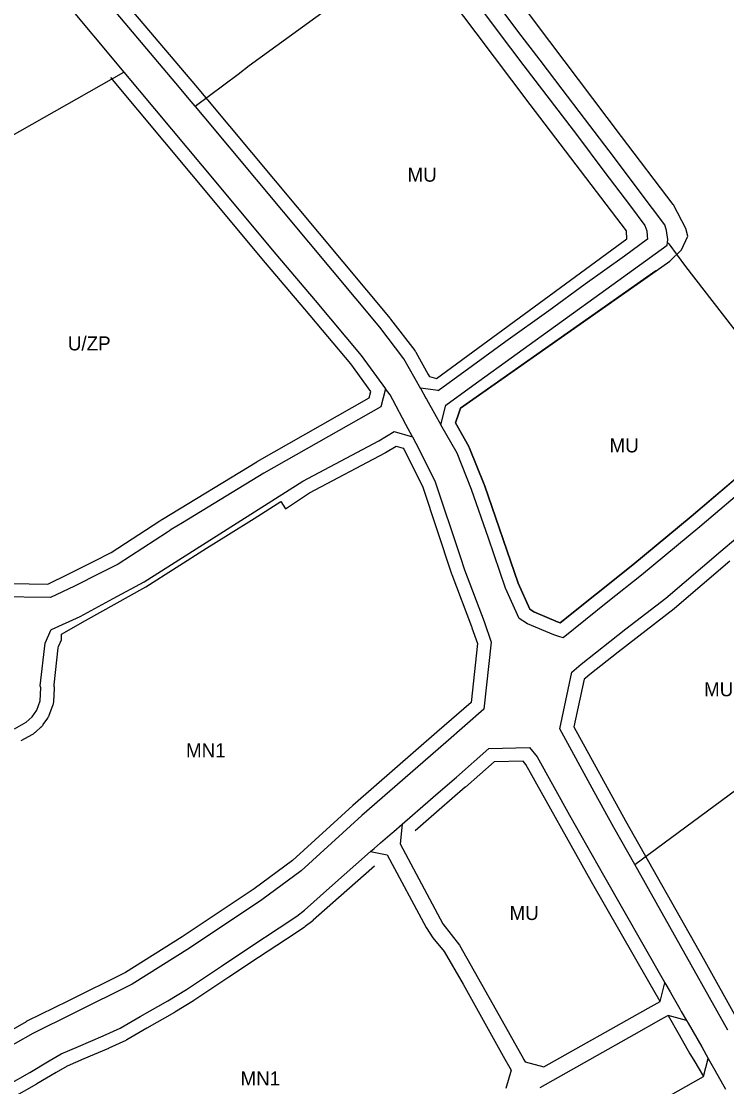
# Model space of a CAD drawing. Extents: x 7435758 to 7439981, y 5550649 to 5554049.
# Drawn here: x 7437381.1 to 7437642.5, y 5551609 to 5552003.8 of the extents above; entities that cross this region are included whole.
import ezdxf

# ---------------------------------------------------------------- set-up
doc = ezdxf.new("R2010")
doc.units = 0
for name, color, linetype in [('linie_rozgraniczające', 7, 'Continuous'), ('linie_zabudowy_nieprzekraczalne', 7, 'Continuous'), ('oznaczenia_przeznaczen', 7, 'Continuous')]:
    doc.layers.add(name, color=color, linetype=linetype)

msp = doc.modelspace()

# ---------------------------------------------------------------- linework, layer by layer
at = {"layer": 'linie_rozgraniczające'}
for p, q in [((7437465.45, 5551987.36), (7437526.53, 5552031.99)), ((7437395.89, 5552012.73), (7437419.08, 5551984.95)), ((7437438.35, 5551980.83), (7437411.17, 5552013.03)), ((7437547.91, 5552013.21), (7437557.39, 5552000.34)), ((7437565.08, 5552000.1), (7437556.73, 5552011.36)), ((7437557.39, 5552000.34), (7437567.31, 5551987.27)), ((7437573.33, 5551989.33), (7437565.08, 5552000.1)), ((7437461.37, 5551984.23), (7437465.45, 5551987.36)), ((7437567.31, 5551987.27), (7437577.08, 5551974.49)), ((7437581.47, 5551978.66), (7437573.33, 5551989.33)), ((7437311.16, 5551923.91), (7437419.08, 5551984.95)), ((7437419.08, 5551984.95), (7437448.05, 5551950.24)), ((7437445.45, 5551972.38), (7437461.37, 5551984.23)), ((7437441.54, 5551977.04), (7437438.35, 5551980.83)), ((7437589.82, 5551967.73), (7437581.47, 5551978.66)), ((7437443.31, 5551974.95), (7437441.54, 5551977.04)), ((7437445.45, 5551972.38), (7437443.31, 5551974.95)), ((7437577.08, 5551974.49), (7437587.18, 5551961.33)), ((7437445.64, 5551972.15), (7437445.45, 5551972.38)), ((7437448.82, 5551968.35), (7437445.64, 5551972.15)), ((7437487.61, 5551921.9), (7437448.82, 5551968.35)), ((7437600.85, 5551953.15), (7437589.82, 5551967.73)), ((7437587.18, 5551961.33), (7437596.99, 5551948.29)), ((7437610.36, 5551940.5), (7437600.85, 5551953.15)), ((7437448.05, 5551950.24), (7437475.42, 5551917.5)), ((7437596.99, 5551948.29), (7437606.8, 5551935.23)), ((7437619.5, 5551928.3), (7437610.36, 5551940.5)), ((7437606.8, 5551935.23), (7437612.15, 5551928.12)), ((7437612.15, 5551928.12), (7437612.9, 5551926.14)), ((7437620.15, 5551926.28), (7437619.5, 5551928.3)), ((7437613.15, 5551923.09), (7437604.55, 5551916.8)), ((7437612.9, 5551926.14), (7437613.06, 5551924.23)), ((7437613.06, 5551924.23), (7437613.15, 5551923.09)), ((7437620.7, 5551922.95), (7437620.15, 5551926.28)), ((7437620.55, 5551921.83), (7437620.7, 5551922.95)), ((7437513.95, 5551890.43), (7437487.61, 5551921.9)), ((7437597.68, 5551904.41), (7437620.42, 5551920.86)), ((7437620.42, 5551920.86), (7437620.55, 5551921.83)), ((7437620.55, 5551921.83), (7437620.98, 5551921.26)), ((7437620.98, 5551921.26), (7437627.25, 5551912.88)), ((7437475.42, 5551917.5), (7437489.95, 5551900.35)), ((7437604.55, 5551916.8), (7437590.08, 5551906.33)), ((7437627.25, 5551912.88), (7437651.38, 5551881.6)), ((7437590.08, 5551906.33), (7437576.52, 5551896.53)), ((7437581.25, 5551892.54), (7437597.68, 5551904.41)), ((7437489.95, 5551900.35), (7437507.05, 5551879.89)), ((7437576.52, 5551896.53), (7437560.63, 5551885.1)), ((7437564.88, 5551880.71), (7437581.25, 5551892.54)), ((7437522.88, 5551878.75), (7437513.95, 5551890.43)), ((7437560.63, 5551885.1), (7437548.22, 5551876.11)), ((7437507.05, 5551879.89), (7437516.05, 5551867.64)), ((7437548.38, 5551868.77), (7437564.88, 5551880.71)), ((7437529.07, 5551867.54), (7437522.88, 5551878.75)), ((7437548.22, 5551876.11), (7437535.57, 5551866.91)), ((7437516.05, 5551867.64), (7437514.27, 5551860.98)), ((7437517.73, 5551865.36), (7437516.05, 5551867.64)), ((7437535.56, 5551866.97), (7437528.99, 5551867.9)), ((7437528.99, 5551867.9), (7437529.07, 5551867.54)), ((7437529.07, 5551867.54), (7437530.96, 5551864.1)), ((7437538.33, 5551861.5), (7437548.38, 5551868.77)), ((7437518.71, 5551863.51), (7437517.73, 5551865.36)), ((7437523.62, 5551854.32), (7437518.71, 5551863.51)), ((7437530.96, 5551864.1), (7437531.18, 5551863.72)), ((7437531.18, 5551863.72), (7437534.16, 5551858.48)), ((7437535.57, 5551866.91), (7437535.56, 5551866.97)), ((7437514.27, 5551860.98), (7437470.98, 5551836.32)), ((7437536.52, 5551854.31), (7437538.33, 5551861.5)), ((7437534.16, 5551858.48), (7437536.52, 5551854.31)), ((7437513.52, 5551848.32), (7437519.26, 5551851.73)), ((7437519.26, 5551851.73), (7437525.99, 5551849.86)), ((7437525.99, 5551849.86), (7437523.62, 5551854.32)), ((7437542.53, 5551843.74), (7437536.52, 5551854.31)), ((7437485.44, 5551833.4), (7437513.52, 5551848.32)), ((7437525.99, 5551849.86), (7437527.24, 5551847.52)), ((7437527.24, 5551847.52), (7437534.32, 5551833.48)), ((7437547.96, 5551830.29), (7437542.53, 5551843.74)), ((7437665.96, 5551844.96), (7437632.46, 5551816.42)), ((7437470.98, 5551836.32), (7437440.82, 5551817.99)), ((7437426.54, 5551796.11), (7437485.44, 5551833.4)), ((7437534.32, 5551833.48), (7437543.64, 5551805.43)), ((7437554.15, 5551812.23), (7437547.96, 5551830.29)), ((7437440.82, 5551817.99), (7437436.65, 5551815.45)), ((7437632.46, 5551816.42), (7437610.86, 5551798.55)), ((7437640.35, 5551807.5), (7437653.28, 5551818.53)), ((7437435.2, 5551814.51), (7437416.9, 5551802.57)), ((7437435.93, 5551815.02), (7437435.2, 5551814.51)), ((7437436.65, 5551815.45), (7437435.93, 5551815.02)), ((7437560.51, 5551793.7), (7437554.15, 5551812.23)), ((7437543.64, 5551805.43), (7437545.26, 5551800.57)), ((7437619.9, 5551790.06), (7437640.35, 5551807.5)), ((7437416.9, 5551802.57), (7437410.33, 5551799.27)), ((7437545.26, 5551800.57), (7437552.55, 5551781.33)), ((7437410.33, 5551799.27), (7437400.82, 5551794.5)), ((7437610.86, 5551798.55), (7437598.45, 5551788.66)), ((7437400.82, 5551794.5), (7437391.92, 5551790.26)), ((7437415.15, 5551789.89), (7437426.54, 5551796.11)), ((7437565.52, 5551782.51), (7437560.51, 5551793.7)), ((7437391.92, 5551790.26), (7437362.95, 5551790.73)), ((7437402.89, 5551783.18), (7437415.15, 5551789.89)), ((7437598.45, 5551788.66), (7437581.81, 5551775.39)), ((7437605.15, 5551778.62), (7437619.9, 5551790.06)), ((7437392.24, 5551778.46), (7437402.89, 5551783.18)), ((7437552.55, 5551781.33), (7437555.16, 5551773.75)), ((7437568.68, 5551780.51), (7437565.52, 5551782.51)), ((7437389.94, 5551773.42), (7437392.15, 5551778.46)), ((7437392.15, 5551778.46), (7437392.24, 5551778.46)), ((7437578.38, 5551776.45), (7437568.68, 5551780.51)), ((7437599.12, 5551773.94), (7437605.15, 5551778.62)), ((7437388.11, 5551757.56), (7437389.94, 5551773.42)), ((7437555.16, 5551773.75), (7437552.52, 5551748.9)), ((7437580.32, 5551775.85), (7437578.38, 5551776.45)), ((7437581.81, 5551775.39), (7437580.32, 5551775.85)), ((7437588.51, 5551765.64), (7437599.12, 5551773.94)), ((7437586.77, 5551764.06), (7437588.51, 5551765.64)), ((7437580.6, 5551741.62), (7437585.14, 5551762.59)), ((7437585.14, 5551762.59), (7437586.77, 5551764.06)), ((7437388.32, 5551756.77), (7437388.11, 5551757.56)), ((7437608.38, 5551691.31), (7437697.86, 5551757.42)), ((7437388.11, 5551752.01), (7437388.32, 5551756.77)), ((7437386.77, 5551748.49), (7437388.11, 5551752.01)), ((7437382.91, 5551744.04), (7437385.05, 5551746.03)), ((7437385.05, 5551746.03), (7437386.77, 5551748.49)), ((7437552.52, 5551748.9), (7437538.38, 5551736.61)), ((7437378.55, 5551741.64), (7437382.91, 5551744.04)), ((7437593.36, 5551718.32), (7437580.6, 5551741.62)), ((7437538.38, 5551736.61), (7437527.95, 5551727.51)), ((7437542.31, 5551723.76), (7437554.35, 5551734.39)), ((7437554.35, 5551734.39), (7437569.37, 5551734.74)), ((7437569.37, 5551734.74), (7437572.2, 5551731.27)), ((7437572.2, 5551731.27), (7437584.28, 5551709.68)), ((7437527.95, 5551727.51), (7437507.26, 5551709.46)), ((7437534.68, 5551717.16), (7437542.31, 5551723.76)), ((7437600.61, 5551705.08), (7437593.36, 5551718.32)), ((7437522.25, 5551706.32), (7437532.65, 5551715.4)), ((7437532.65, 5551715.4), (7437534.68, 5551717.16)), ((7437584.28, 5551709.68), (7437596.77, 5551687.35)), ((7437507.26, 5551709.46), (7437484.74, 5551689.01)), ((7437519.07, 5551703.54), (7437522.25, 5551706.32)), ((7437522.25, 5551706.32), (7437521.46, 5551699.07)), ((7437514.23, 5551699.39), (7437518.5, 5551703.04)), ((7437518.5, 5551703.04), (7437519.07, 5551703.54)), ((7437608.38, 5551691.31), (7437600.61, 5551705.08)), ((7437511.81, 5551697.32), (7437514.23, 5551699.39)), ((7437521.46, 5551699.07), (7437537.32, 5551669.37)), ((7437495.3, 5551682.7), (7437510.51, 5551696.17)), ((7437510.51, 5551696.17), (7437511.81, 5551697.32)), ((7437510.51, 5551696.17), (7437516.65, 5551694.89)), ((7437516.65, 5551694.89), (7437531.04, 5551668.06)), ((7437629.36, 5551654.17), (7437608.38, 5551691.31)), ((7437484.74, 5551689.01), (7437470.2, 5551678.27)), ((7437596.77, 5551687.35), (7437618.93, 5551648.65)), ((7437485.95, 5551674.45), (7437495.3, 5551682.7)), ((7437470.2, 5551678.27), (7437443.4, 5551660.3)), ((7437483.17, 5551672.24), (7437485.95, 5551674.45)), ((7437476.57, 5551667.91), (7437483.17, 5551672.24)), ((7437466.18, 5551661.02), (7437476.57, 5551667.91)), ((7437531.04, 5551668.06), (7437533.57, 5551664.2)), ((7437537.32, 5551669.37), (7437543.45, 5551661.43)), ((7437533.57, 5551664.2), (7437537.74, 5551659.09)), ((7437443.4, 5551660.3), (7437422.12, 5551647)), ((7437455.22, 5551653.73), (7437466.18, 5551661.02)), ((7437537.74, 5551659.09), (7437544.83, 5551646.97)), ((7437543.45, 5551661.43), (7437557.1, 5551637.43)), ((7437442.25, 5551645.05), (7437455.22, 5551653.73)), ((7437642.86, 5551629.92), (7437629.36, 5551654.17)), ((7437422.12, 5551647), (7437400.48, 5551636.23)), ((7437544.83, 5551646.97), (7437560.31, 5551619.28)), ((7437617.81, 5551640.65), (7437619.59, 5551647.49)), ((7437618.93, 5551648.65), (7437619.59, 5551647.49)), ((7437619.59, 5551647.49), (7437621.5, 5551644.17)), ((7437435.36, 5551640.86), (7437442.25, 5551645.05)), ((7437621.5, 5551644.17), (7437622.11, 5551643.1)), ((7437622.11, 5551643.1), (7437625.09, 5551637.89)), ((7437425.1, 5551635.06), (7437435.36, 5551640.86)), ((7437613.33, 5551638.1), (7437617.81, 5551640.65)), ((7437400.48, 5551636.23), (7437385.3, 5551628.76)), ((7437417.69, 5551630.74), (7437425.1, 5551635.06)), ((7437557.1, 5551637.43), (7437567.16, 5551619.38)), ((7437574.65, 5551616.33), (7437613.33, 5551638.1)), ((7437620.74, 5551635.41), (7437618.01, 5551633.86)), ((7437627.56, 5551633.58), (7437620.74, 5551635.41)), ((7437625.09, 5551637.89), (7437625.65, 5551636.91)), ((7437625.65, 5551636.91), (7437627.56, 5551633.58)), ((7437411.37, 5551627.82), (7437417.69, 5551630.74)), ((7437618.01, 5551633.86), (7437608.04, 5551628.18)), ((7437627.56, 5551633.58), (7437628.17, 5551632.51)), ((7437628.17, 5551632.51), (7437633.2, 5551623.74)), ((7437385.3, 5551628.76), (7437365.21, 5551617.29)), ((7437402.23, 5551623.95), (7437411.37, 5551627.82)), ((7437608.04, 5551628.18), (7437573.23, 5551608.58)), ((7437395.88, 5551621.14), (7437402.23, 5551623.95)), ((7437633.2, 5551623.74), (7437635.6, 5551619.51)), ((7437391.43, 5551618.66), (7437395.88, 5551621.14)), ((7437560.31, 5551619.28), (7437562.05, 5551616.05)), ((7437567.16, 5551619.38), (7437567.22, 5551619.26)), ((7437567.22, 5551619.26), (7437567.79, 5551618.25)), ((7437633.83, 5551612.74), (7437635.6, 5551619.51)), ((7437635.6, 5551619.51), (7437638.09, 5551615.13)), ((7437384.27, 5551614.31), (7437391.43, 5551618.66)), ((7437562.56, 5551615.13), (7437560.61, 5551608.31)), ((7437562.05, 5551616.05), (7437562.56, 5551615.13)), ((7437567.79, 5551618.25), (7437574.65, 5551616.33)), ((7437638.09, 5551615.13), (7437642.09, 5551608.09)), ((7437375.99, 5551609.64), (7437384.27, 5551614.31)), ((7437578.11, 5551581.52), (7437633.83, 5551612.74))]:
    msp.add_line(p, q, dxfattribs=at)
at = {"layer": 'linie_zabudowy_nieprzekraczalne'}
for p, q in [((7437543.84, 5551860.45), (7437616.32, 5551911.33)), ((7437543.17, 5551858.56), (7437543.84, 5551860.45)), ((7437541.94, 5551855.04), (7437543.17, 5551858.56)), ((7437541.91, 5551854.96), (7437541.94, 5551855.04)), ((7437546.88, 5551846.21), (7437541.91, 5551854.96)), ((7437546.92, 5551846.13), (7437546.88, 5551846.21)), ((7437547.07, 5551845.84), (7437546.92, 5551846.13)), ((7437547.17, 5551845.61), (7437547.07, 5551845.84)), ((7437552.59, 5551832.16), (7437547.17, 5551845.61)), ((7437661.22, 5551847.49), (7437629.25, 5551820.25)), ((7437552.62, 5551832.09), (7437552.59, 5551832.16)), ((7437552.69, 5551831.91), (7437552.62, 5551832.09)), ((7437565.16, 5551795.53), (7437552.69, 5551831.91)), ((7437629.25, 5551820.25), (7437607.71, 5551802.43)), ((7437607.71, 5551802.43), (7437580.76, 5551780.95)), ((7437569.47, 5551785.93), (7437565.16, 5551795.53)), ((7437571, 5551784.96), (7437569.47, 5551785.93)), ((7437580.08, 5551781.16), (7437571, 5551784.96)), ((7437580.76, 5551780.95), (7437580.08, 5551781.16))]:
    msp.add_line(p, q, dxfattribs=at)
for points in [[(7437415.01, 5552016.22), (7437445.57, 5551979.99), (7437450.09, 5551974.62), (7437491.45, 5551925.11), (7437517.78, 5551893.63), (7437517.79, 5551893.63), (7437517.92, 5551893.46), (7437526.85, 5551881.78), (7437526.93, 5551881.69), (7437527.11, 5551881.42), (7437527.26, 5551881.16), (7437531.84, 5551872.87), (7437532.2, 5551872.23), (7437532.3, 5551872.2), (7437534.97, 5551871.39), (7437605.41, 5551923.13), (7437605.29, 5551925.97), (7437605.29, 5551926.09), (7437569.67, 5551972.95), (7437569.66, 5551972.96), (7437549.64, 5551999.44), (7437549.63, 5551999.46), (7437526.05, 5552030.9)], [(7437616.32, 5551911.33), (7437621.41, 5551914.9), (7437625.71, 5551919.12), (7437628.13, 5551924.17), (7437627.38, 5551927.03), (7437622.72, 5551935.79), (7437622.67, 5551935.85), (7437603.54, 5551961.13), (7437576.99, 5551996.35), (7437552.66, 5552028.7)], [(7437363.06, 5551795.73), (7437390.83, 5551795.28), (7437398.62, 5551798.99), (7437408.09, 5551803.74), (7437414.4, 5551806.91), (7437432.41, 5551818.65), (7437433.08, 5551819.12), (7437433.26, 5551819.24), (7437433.34, 5551819.29), (7437468.39, 5551840.59), (7437468.51, 5551840.66), (7437509.98, 5551864.29), (7437510.6, 5551866.62), (7437503.12, 5551876.81), (7437486.12, 5551897.13), (7437471.61, 5551914.27), (7437471.58, 5551914.3), (7437444.22, 5551947.04), (7437444.22, 5551947.04), (7437414.28, 5551982.9)], [(7437616.27, 5551911.29), (7437543.84, 5551860.45), (7437543.17, 5551858.56), (7437541.94, 5551855.04), (7437541.91, 5551854.96), (7437546.88, 5551846.21), (7437546.92, 5551846.13), (7437547.07, 5551845.84), (7437547.17, 5551845.61), (7437552.59, 5551832.16), (7437552.62, 5551832.09), (7437552.69, 5551831.91), (7437565.16, 5551795.53), (7437569.47, 5551785.93), (7437571, 5551784.96), (7437580.08, 5551781.16), (7437580.76, 5551780.95), (7437607.71, 5551802.43), (7437629.25, 5551820.25), (7437661.22, 5551847.49)], [(7437380.97, 5551737.26), (7437385.32, 5551739.66), (7437385.58, 5551739.82), (7437385.85, 5551740), (7437386.11, 5551740.2), (7437386.3, 5551740.37), (7437388.45, 5551742.35), (7437388.5, 5551742.4), (7437388.73, 5551742.64), (7437388.94, 5551742.88), (7437389.14, 5551743.15), (7437389.15, 5551743.17), (7437390.87, 5551745.63), (7437391.03, 5551745.88), (7437391.19, 5551746.16), (7437391.34, 5551746.46), (7437391.44, 5551746.71), (7437392.78, 5551750.22), (7437392.8, 5551750.28), (7437392.9, 5551750.59), (7437392.99, 5551750.91), (7437393.05, 5551751.23), (7437393.09, 5551751.55), (7437393.1, 5551751.78), (7437393.32, 5551756.55), (7437393.32, 5551756.65), (7437393.32, 5551756.97), (7437393.29, 5551757.3), (7437393.25, 5551757.62), (7437393.18, 5551757.93), (7437393.19, 5551757.94), (7437394.76, 5551771.61), (7437394.82, 5551772.1), (7437395.93, 5551774.63), (7437395.97, 5551776.64), (7437404.9, 5551781.71), (7437427.15, 5551794.29), (7437449.65, 5551808.57), (7437457.8, 5551813.65), (7437467.38, 5551819.51), (7437477.21, 5551825.88), (7437478.97, 5551823.1), (7437487.89, 5551829.04), (7437515.87, 5551843.9), (7437515.91, 5551843.93), (7437516.08, 5551844.02), (7437519.96, 5551846.33), (7437519.98, 5551846.34), (7437522.59, 5551845.62), (7437522.8, 5551845.21), (7437529.69, 5551831.56), (7437540.51, 5551798.99), (7437540.58, 5551798.79), (7437547.87, 5551779.56), (7437547.88, 5551779.53), (7437548.01, 5551779.23), (7437548.08, 5551779.1), (7437550.07, 5551773.18), (7437547.75, 5551751.39), (7437535.1, 5551740.38), (7437535.1, 5551740.37), (7437503.97, 5551713.23), (7437503.9, 5551713.16), (7437481.57, 5551692.88), (7437467.33, 5551682.35), (7437440.68, 5551664.5), (7437419.67, 5551651.37), (7437398.25, 5551640.71), (7437383.09, 5551633.25), (7437382.91, 5551633.15), (7437382.82, 5551633.1), (7437362.73, 5551621.63)], [(7437643.59, 5551803.69), (7437623.14, 5551786.26), (7437623.1, 5551786.22), (7437622.96, 5551786.11), (7437602.2, 5551770), (7437591.73, 5551761.81), (7437590.12, 5551760.35), (7437589.69, 5551759.96), (7437585.88, 5551742.38), (7437604.97, 5551707.51), (7437633.71, 5551656.63), (7437633.73, 5551656.6), (7437646.55, 5551633.57)], [(7437617.81, 5551640.65), (7437613.59, 5551647.91), (7437592.43, 5551684.87), (7437592.4, 5551684.91), (7437568.05, 5551728.45), (7437567.04, 5551729.68), (7437556.29, 5551729.44), (7437545.62, 5551720.02), (7437545.58, 5551719.98), (7437535.93, 5551711.63), (7437527.01, 5551703.84)], [(7437511.95, 5551690.76), (7437498.62, 5551678.95), (7437498.61, 5551678.95), (7437489.26, 5551670.7), (7437489.15, 5551670.61), (7437489.07, 5551670.54), (7437486.29, 5551668.33), (7437486.12, 5551668.2), (7437485.91, 5551668.05), (7437479.32, 5551663.74), (7437468.95, 5551656.86), (7437457.99, 5551649.56), (7437445.03, 5551640.9), (7437444.92, 5551640.83), (7437444.85, 5551640.78), (7437437.96, 5551636.59), (7437437.82, 5551636.51), (7437427.59, 5551630.72), (7437420.21, 5551626.42), (7437420.08, 5551626.34), (7437419.79, 5551626.2), (7437419.78, 5551626.2), (7437413.47, 5551623.28), (7437413.32, 5551623.22), (7437404.22, 5551619.37), (7437398.11, 5551616.67), (7437393.95, 5551614.34), (7437386.86, 5551610.03), (7437386.72, 5551609.96), (7437378.45, 5551605.28)], [(7437620.74, 5551635.41), (7437624.84, 5551628.27), (7437628.86, 5551621.26), (7437630.25, 5551618.8), (7437633.83, 5551612.74)]]:
    msp.add_lwpolyline(points, dxfattribs=at)

# ---------------------------------------------------------------- texts
at = {"layer": 'oznaczenia_przeznaczen'}
for s, p in [('MU', (7437524.19, 5551944.33)), ('U/ZP', (7437398.32, 5551881.83)), ('MU', (7437599.06, 5551844.03)), ('MU', (7437634.09, 5551753.68)), ('MN1', (7437442.1, 5551731.03)), ('MU', (7437561.99, 5551670.78)), ('MN1', (7437462.3, 5551609.47))]:
    msp.add_text(s, height=5.2, dxfattribs=at).set_placement(p)

doc.saveas('drawing.dxf')
